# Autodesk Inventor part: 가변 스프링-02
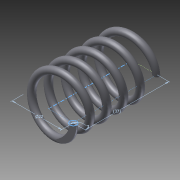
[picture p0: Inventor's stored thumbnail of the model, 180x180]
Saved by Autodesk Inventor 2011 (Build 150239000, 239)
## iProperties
Created: 2015-05
Part Number: 가변 스프링-02
Document SubType Name: Modeling
Designer: Administrator
Density: 7.87 g/cm^3
Material: 탄소강
Mass: 18.8475 g
Surface Area: 32.4803 cm^2
Volume: 2.39485 cm^3
Author: Administrator
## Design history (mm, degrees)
sketch "스케치1"
  geometry: L1 (0, 0)-(11, 0); L2 (11, 0)-(11, 36.411); L3 (11, 36.411)-(0, 36.411); L4 (0, 36.411)-(0, 0); C1 r 1.5 at (11, 0)
  constraints: 8 end point, 2 parallel, 1 centre point, 1 coincident, 1 horizontal, 1 perpendicular
  dimensions: "d0" = 3 diameter of C1; "d1" = 22 diameter of L2 L4; "d2" = 36.4112 distance of L1.end L2.end (derived)
feature "코일1" sketch "스케치1" pitch "d3" = 10; turns "d5" = 5; dims "d4" = 36.4112 (= d2), "d6" = 0, angle "d7" = 90 deg, angle "d8" = 90 deg, "d9" = 0, "d10" = 0
node "작업 평면1"
sketch "스케치2"
  geometry: L1 (0, 0)-(3, 0) reference; 1 further point
  constraints: 1 horizontal alignment
extrude "돌출1" cut sketch "스케치2" distance "d11" = 10; taper "d12" = 0 deg
node "작업 평면2"
sketch "스케치3"
  geometry: L1 (3, 0)-(0, 0) reference; 1 further point
  constraints: 1 horizontal alignment
extrude "돌출2" cut sketch "스케치3" stored distance "d13" = 10; taper "d14" = 0 deg
node "솔리드1"
node "절단 모서리 투영1"
node "절단 모서리 투영2"
